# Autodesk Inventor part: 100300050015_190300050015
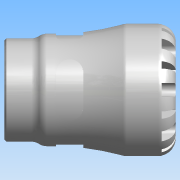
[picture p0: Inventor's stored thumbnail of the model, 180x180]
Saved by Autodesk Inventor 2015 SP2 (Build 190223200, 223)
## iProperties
Created: 2016-12
Part Number: 100300050015_190300050015
Material: PVC-Piping
Description: PLASSON FEMALE ADAPTOR 50X1.1/2" SERIES 1
Document SubType Name: Modeling
Designer: KIM
Mass: 664.223 g
Surface Area: 733.008 cm^2
Volume: 474.445 cm^3
Density: 1.4 g/cm^3
Appearance: Smooth - White
Author: KIM
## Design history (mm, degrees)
derived "1003.ipt"
feature "Solid1::1003.ipt"
tag "TaggingFeature1"
body "Solid1"
other parameters: "d1" = 32.76, "d3" = 62.5, "d4" = 85, "d6" = 78, "d8" = 72.25, "d13" = 9, "d14" = 9, "d15" = 0, "d17" = 360 deg, "d19" = 8 deg, "d20" = 1, "d21" = 1, "d22" = 8 deg, "d24" = 0, "d26" = 360 deg, "d32" = 8.5, "d33" = 8.5, "d39" = 1.34535, "d42" = 44.845, "d43" = 66.3, "d46" = 4.16667, "d47" = 24, "d48" = 42.60275, "d50" = 2.64, "d51" = 0.85, "d54" = 17.5, "d55" = 11, "d57" = 17.64, "d58" = 0, "d68" = 360 deg, "d72" = 1, "d74" = 0, "d76" = 14.875, "E_" = 85, "l_" = 78, "Rp" = 44.845, "l_2" = 24, "d9" = 11.25, "d11" = 85, "d12" = 62.5, "d49" = 8
